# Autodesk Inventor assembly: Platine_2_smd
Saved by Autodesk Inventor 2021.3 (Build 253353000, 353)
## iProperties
Created: 2023-03
Part Number: Platine_2_smd
Document SubType Name: Assembly
Designer: AdminForWorker
Title: Platine_2_smd v2
Author: AdminForWorker
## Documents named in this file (3)
- z:\worker\convert-fusion-r08-cosv3\tmp\job-1\3553\output\files\82b4d9ad-b575-4129-b9ca-4964d6b72adf\Platine_2_smd v2.iam
- z:\worker\convert-fusion-r08-cosv3\tmp\job-1\3553\output\files\82b4d9ad-b575-4129-b9ca-4964d6b72adf\Board_1.ipt
- z:\worker\convert-fusion-r08-cosv3\tmp\job-1\3553\output\files\82b4d9ad-b575-4129-b9ca-4964d6b72adf\Packages.iam
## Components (2 placed, 2 different names)
1. Board:1
2. Packages:1 [sub-assembly]
